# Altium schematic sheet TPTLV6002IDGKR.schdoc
size 127 x 101 mm
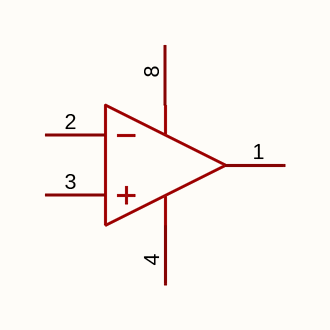
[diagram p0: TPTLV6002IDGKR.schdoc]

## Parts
U?  tptlv6002idgkr  [MSOP-8_L3.0-W3.0-P0.65-LS5.0-BL]  (value not drawn)  (part A of 2)

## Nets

Not connected (* = marked no-connect by the designer): U? 1(OUTA) 2(INA-) 3(INA+) 4(VSS) 8(VDD)

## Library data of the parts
U? = tptlv6002idgkr: 放大器数:2;轨到轨:轨到轨输入,轨到轨输出;增益带宽积(GBW):1MHz;输入失调电压(Vos):5mV;压摆率(SR):600V/ms;输入偏置电流(Ib):-;; Manufacturer: TECH PUBLIC(台舟); AddInBom: yes; ModelId: 1de5a054e9244f539c6db8238d445f94; ModelTransform: 118.11,196.85,0,0,0,0,0,0,0; Number of Channels: 2; Maximum Power Supply Range (Vdd-Vss): 5.5V; Gain Bandwidth Product: 1MHz; Vos - Input Offset Voltage: 5mV; Input Offset Voltage Drift(Vos TC): 2uV/℃; Input Voltage Noise Density: 20nV/√Hz@10kHz; Common Mode Rejection Ratio(CMRR): 65dB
